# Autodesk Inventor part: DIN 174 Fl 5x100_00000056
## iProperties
Created: 2006-03
Part Number: DIN 174 Fl 5x100_00000056
Material: Default
Document SubType Name: Modeling
Designer: Carlo
Stock Number: DIN 174 Fl 5x100
Mass: 891.925 g
Surface Area: 3756.29 cm^2
Volume: 891.925 cm^3
Density: 1 g/cm^3
G_L: 1783.948 mm
G_W: 5.000 mm
G_H: 100.000 mm
AFG_Item: 100 x 5
CSToolsMass: 1.0
CSToolsVolume: 891925.0
CSToolsArea: 3756.0
Author: Carlo
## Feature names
1. AFG_Detailed_DIN 174 Fl 5x100_00000056 [Extrusion]
2. AFG_Simplified_DIN 174 Fl 5x100_00000056 [Extrusion]
3. AFG_EndExtrusion_1 [Extrusion]
4. AFG_EndExtrusion_2 [Extrusion]
